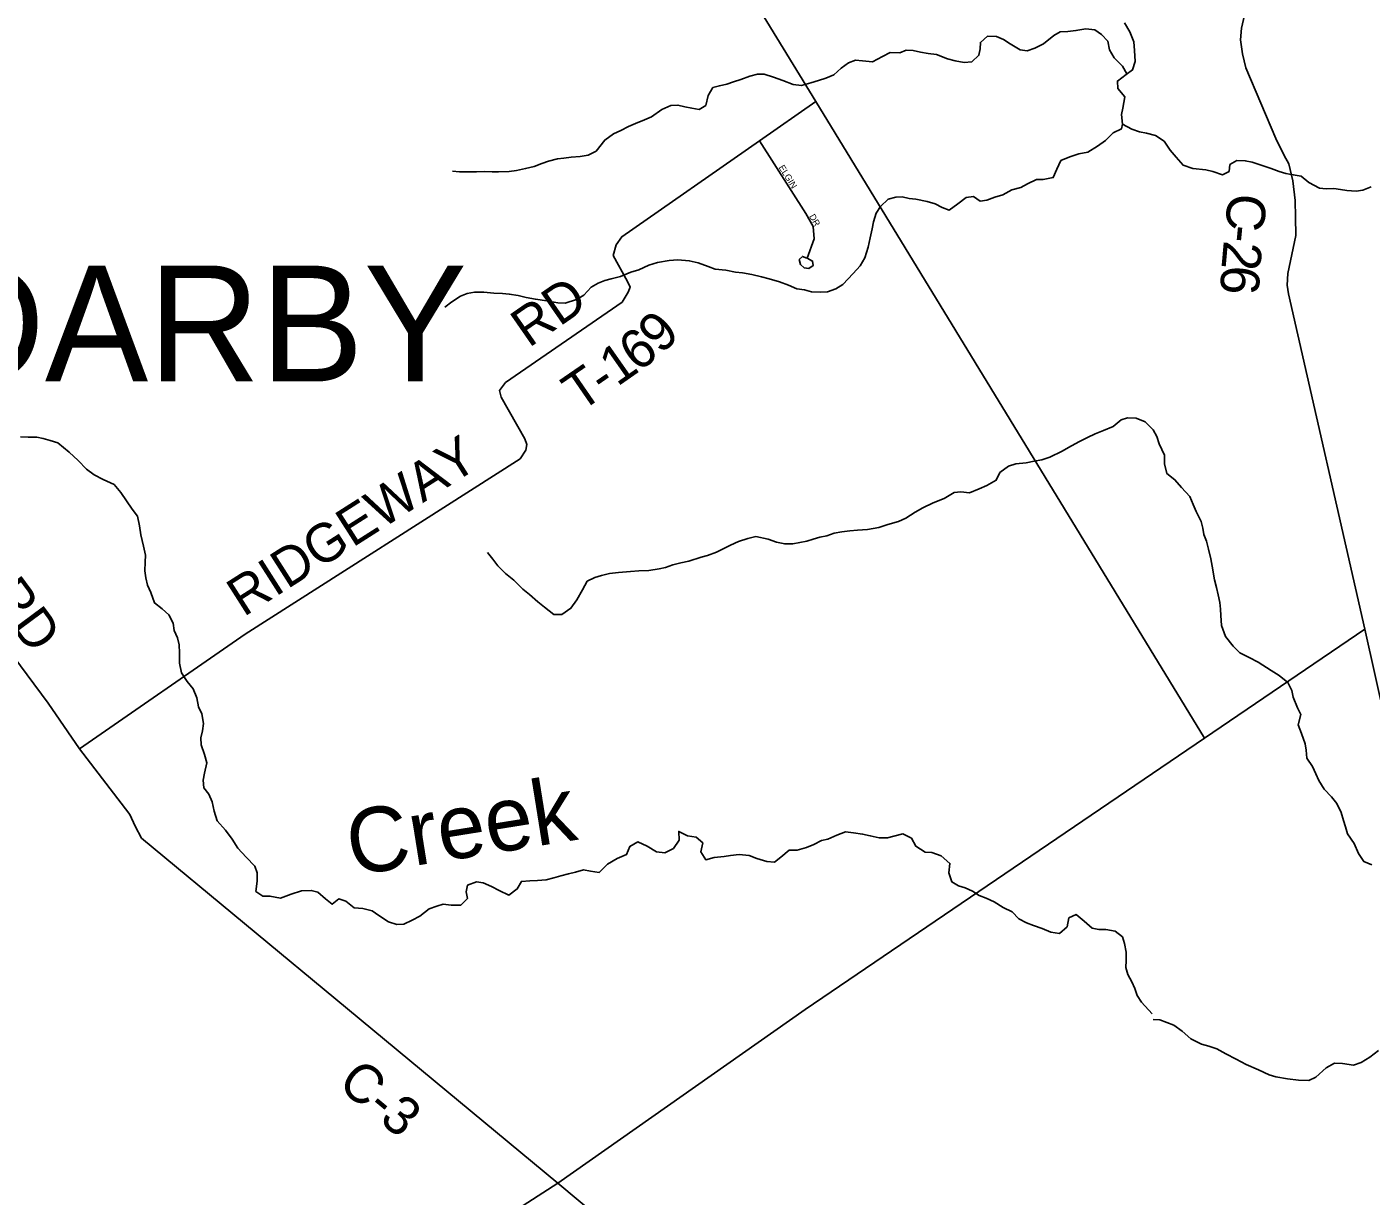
# Model space of a CAD drawing. Extents: x 1643459 to 2064572, y 425441 to 780708.
# Drawn here: x 1773348 to 1783780, y 636662 to 645736 of the extents above; entities that cross this region are included whole.
import ezdxf

# ---------------------------------------------------------------- set-up
doc = ezdxf.new("R2010")
doc.units = 0
for name, color, linetype in [('GM_X_Adjacent_County_Text', 7, 'Continuous'), ('GM_X_County', 7, 'Continuous'), ('GM_X_Interchange_Ramps', 7, 'Continuous'), ('GM_X_Major_River', 7, 'Continuous'), ('GM_X_Major_River_Text', 7, 'Continuous'), ('GM_X_Minor_Lake', 7, 'Continuous'), ('GM_X_Section_Text', 7, 'Continuous'), ('GM_X_Township', 7, 'Continuous'), ('GM_X_US_Route', 7, 'Continuous')]:
    doc.layers.add(name, color=color, linetype=linetype)

msp = doc.modelspace()

# ---------------------------------------------------------------- linework, layer by layer
at = {"layer": 'GM_X_County'}
msp.add_lwpolyline([(1779401, 643942), (1779367, 643955), (1779342, 643932), (1779351, 643892), (1779380, 643867), (1779416, 643862), (1779449, 643883), (1779445, 643919), (1779403, 643942), (1779459, 644090), (1779450, 644186), (1779392, 644289), (1779033, 644851)], dxfattribs=at)
at = {"layer": 'GM_X_Major_River_Text'}
for points in [[(1773772, 654062), (1774788, 652619), (1775038, 652262), (1776783, 649553), (1777290, 648723), (1777849, 647808), (1778173, 647353), (1778816, 646270), (1779041, 645859), (1779471, 645156), (1782488, 640217)], [(1779471, 645156), (1779033, 644851), (1777965, 644107), (1777921, 644045), (1777899, 643961), (1778009, 643759), (1778029, 643717), (1778015, 643677), (1777967, 643599), (1777063, 642975), (1777017, 642915), (1777029, 642863), (1777213, 642538), (1777229, 642494), (1777221, 642450), (1777177, 642384), (1775043, 641022), (1773757, 640134)]]:
    msp.add_lwpolyline(points, dxfattribs=at)
at = {"layer": 'GM_X_Minor_Lake'}
for points in [[(1782846, 646043), (1782774, 645727), (1782766, 645635), (1782783, 645526), (1782809, 645418), (1783041, 644870), (1783105, 644738), (1783143, 644674), (1783173, 644541), (1783191, 644389), (1783194, 644259), (1783196, 644117), (1783134, 643823), (1783128, 643731), (1783140, 643665), (1783732, 641062), (1783977, 639959), (1784007, 639839), (1784401, 639056), (1784510, 638910), (1784732, 638676), (1785248, 638277), (1786244, 637616)], [(1772273, 642156), (1773514, 640487), (1773757, 640134), (1774079, 639712), (1774147, 639624), (1774189, 639534), (1774237, 639440), (1775835, 638115), (1777468, 636763)], [(1777468, 636763), (1779387, 638110), (1782488, 640217), (1783732, 641062)], [(1770002, 630601), (1770093, 632687), (1770093, 632721), (1770134, 632749), (1771962, 632990), (1772032, 633004), (1772074, 633002), (1772101, 633006), (1772127, 633040), (1772487, 633676), (1772513, 633722), (1772573, 633755), (1773397, 634171), (1773574, 634266), (1774462, 634825), (1777468, 636763)], [(1777468, 636763), (1779643, 634945), (1780949, 633862), (1781378, 633511), (1781747, 633198), (1782023, 632988), (1782140, 632869), (1782345, 632675), (1782447, 632557), (1782718, 632238), (1783038, 631872), (1783242, 631666), (1783288, 631620)]]:
    msp.add_lwpolyline(points, dxfattribs=at)
at = {"layer": 'GM_X_US_Route'}
for points in [[(1781884, 645372), (1781852, 645430), (1781786, 645495), (1781751, 645559), (1781737, 645625), (1781689, 645677), (1781635, 645714), (1781567, 645722), (1781489, 645708), (1781427, 645699), (1781367, 645697), (1781317, 645669), (1781238, 645605), (1781170, 645572), (1781110, 645550), (1781056, 645558), (1780980, 645605), (1780926, 645639), (1780872, 645661), (1780802, 645664), (1780748, 645616), (1780746, 645566), (1780737, 645516), (1780681, 645464), (1780623, 645460), (1780551, 645473), (1780493, 645489), (1780407, 645523), (1780343, 645530), (1780283, 645540), (1780225, 645554), (1780173, 645556), (1780123, 645535), (1780047, 645537), (1779989, 645505), (1779910, 645466), (1779834, 645472), (1779778, 645478), (1779724, 645457), (1779668, 645415), (1779610, 645363), (1779548, 645337), (1779491, 645321), (1779431, 645302), (1779359, 645280), (1779295, 645290), (1779215, 645319), (1779141, 645347), (1779069, 645368), (1779017, 645368), (1778959, 645354), (1778889, 645328), (1778831, 645309), (1778779, 645291), (1778723, 645279), (1778672, 645265), (1778634, 645204), (1778618, 645126), (1778566, 645096), (1778508, 645106), (1778454, 645116), (1778400, 645129), (1778345, 645127), (1778275, 645095), (1778195, 645037), (1778141, 645016), (1778071, 644986), (1778016, 644964), (1777958, 644933), (1777900, 644907), (1777832, 644857), (1777765, 644771), (1777705, 644740), (1777641, 644730), (1777573, 644726), (1777515, 644718), (1777465, 644711), (1777395, 644693), (1777345, 644675), (1777284, 644652), (1777218, 644636), (1777148, 644622), (1777092, 644614), (1777008, 644611), (1776958, 644611), (1776896, 644613), (1776838, 644612), (1776760, 644610), (1776706, 644610), (1776650, 644617)], [(1783782, 644496), (1783716, 644470), (1783664, 644461), (1783592, 644465), (1783542, 644475), (1783492, 644481), (1783431, 644478), (1783379, 644484), (1783298, 644528), (1783238, 644577), (1783176, 644589), (1783118, 644599), (1783066, 644614), (1783004, 644636), (1782928, 644662), (1782858, 644685), (1782804, 644697), (1782738, 644699), (1782684, 644667), (1782679, 644615), (1782627, 644588), (1782551, 644614), (1782497, 644626), (1782397, 644637), (1782321, 644663), (1782267, 644725), (1782220, 644780), (1782174, 644850), (1782108, 644892), (1782036, 644911), (1781984, 644921), (1781922, 644943), (1781852, 644980), (1781842, 645056), (1781853, 645106), (1781869, 645192), (1781815, 645258), (1781812, 645316), (1781878, 645366), (1781928, 645402), (1781948, 645468), (1781945, 645552), (1781939, 645620), (1781907, 645698), (1781866, 645767)], [(1781852, 644980), (1781842, 644944), (1781778, 644914), (1781718, 644854), (1781657, 644810), (1781583, 644765), (1781511, 644751), (1781441, 644727), (1781373, 644698), (1781340, 644632), (1781314, 644566), (1781234, 644552), (1781184, 644552), (1781113, 644519), (1781063, 644489), (1780991, 644471), (1780921, 644432), (1780859, 644414), (1780797, 644390), (1780747, 644384), (1780695, 644419), (1780637, 644413), (1780574, 644363), (1780506, 644313), (1780450, 644334), (1780396, 644364), (1780334, 644380), (1780246, 644399), (1780196, 644403), (1780142, 644417), (1780092, 644414), (1780032, 644400), (1779972, 644342), (1779939, 644290), (1779919, 644222), (1779907, 644168), (1779893, 644098), (1779878, 644026), (1779852, 643944), (1779814, 643882), (1779761, 643821), (1779681, 643737), (1779625, 643703), (1779562, 643679), (1779506, 643678), (1779438, 643680), (1779384, 643696), (1779324, 643703), (1779258, 643731), (1779190, 643757), (1779108, 643782), (1779048, 643796), (1778974, 643814), (1778902, 643827), (1778848, 643833), (1778772, 643847), (1778690, 643856), (1778634, 643876), (1778558, 643906), (1778488, 643921), (1778400, 643927), (1778332, 643922), (1778242, 643908), (1778176, 643886), (1778098, 643851), (1778036, 643833), (1777955, 643799), (1777883, 643782), (1777833, 643768), (1777781, 643746), (1777727, 643716), (1777669, 643655), (1777614, 643621), (1777526, 643591), (1777468, 643595), (1777382, 643610), (1777294, 643622), (1777224, 643635), (1777160, 643651), (1777092, 643663), (1777040, 643666), (1776972, 643670), (1776894, 643678), (1776822, 643677), (1776766, 643667), (1776712, 643645), (1776645, 643601), (1776591, 643560)], [(1783785, 639234), (1783723, 639259), (1783682, 639321), (1783648, 639399), (1783598, 639473), (1783582, 639528), (1783567, 639578), (1783547, 639640), (1783515, 639708), (1783473, 639760), (1783415, 639819), (1783374, 639887), (1783352, 639939), (1783326, 639997), (1783282, 640062), (1783275, 640122), (1783269, 640172), (1783239, 640252), (1783215, 640320), (1783234, 640400), (1783208, 640452), (1783176, 640533), (1783164, 640585), (1783135, 640649), (1783067, 640703), (1783005, 640740), (1782905, 640806), (1782835, 640841), (1782761, 640879), (1782710, 640931), (1782650, 641006), (1782618, 641090), (1782614, 641168), (1782611, 641218), (1782605, 641268), (1782593, 641328), (1782581, 641386), (1782566, 641444), (1782546, 641551), (1782536, 641607), (1782517, 641683), (1782503, 641745), (1782483, 641797), (1782475, 641847), (1782461, 641897), (1782422, 641976), (1782398, 642030), (1782374, 642092), (1782310, 642162), (1782257, 642221), (1782195, 642269), (1782177, 642345), (1782177, 642413), (1782136, 642500), (1782116, 642556), (1782088, 642608), (1782026, 642670), (1781956, 642699), (1781890, 642703), (1781840, 642687), (1781778, 642634), (1781704, 642604), (1781638, 642578), (1781579, 642550), (1781511, 642517), (1781433, 642471), (1781383, 642443), (1781287, 642398), (1781226, 642376), (1781166, 642366), (1781102, 642354), (1781024, 642345), (1780966, 642327), (1780898, 642277), (1780871, 642217), (1780799, 642176), (1780739, 642150), (1780663, 642120), (1780597, 642129), (1780545, 642123), (1780468, 642075), (1780382, 642042), (1780300, 642004), (1780242, 641970), (1780169, 641924), (1780113, 641897), (1780029, 641873), (1779959, 641851), (1779873, 641836), (1779793, 641830), (1779735, 641824), (1779673, 641817), (1779612, 641807), (1779556, 641787), (1779502, 641776)], [(1776768, 638972), (1776715, 638920), (1776641, 638920), (1776579, 638927), (1776529, 638913), (1776471, 638891), (1776397, 638834), (1776338, 638804), (1776274, 638772), (1776220, 638770), (1776154, 638791), (1776080, 638841), (1776028, 638877), (1775954, 638894), (1775888, 638898), (1775824, 638952), (1775770, 638969), (1775718, 638927), (1775666, 638969), (1775607, 639022), (1775555, 639034), (1775480, 639030), (1775398, 639005), (1775316, 638975), (1775234, 638991), (1775180, 638990), (1775124, 639026), (1775136, 639106), (1775135, 639172), (1775117, 639222), (1775049, 639293), (1774985, 639363), (1774940, 639433), (1774888, 639502), (1774824, 639574), (1774802, 639650), (1774785, 639722), (1774759, 639781), (1774721, 639831), (1774717, 639891), (1774726, 639945), (1774744, 640025), (1774726, 640089), (1774701, 640165), (1774697, 640219), (1774711, 640273), (1774719, 640329), (1774706, 640404), (1774680, 640458), (1774668, 640528), (1774638, 640598), (1774591, 640656), (1774547, 640723), (1774533, 640799), (1774533, 640879), (1774530, 640941), (1774516, 640995), (1774492, 641051), (1774482, 641109), (1774449, 641174), (1774397, 641220), (1774339, 641266), (1774311, 641347), (1774283, 641403), (1774272, 641459), (1774262, 641515), (1774266, 641581), (1774268, 641635), (1774253, 641705), (1774233, 641795), (1774221, 641864), (1774206, 641938), (1774166, 641992), (1774122, 642058), (1774076, 642123), (1774025, 642185), (1773941, 642223), (1773869, 642260), (1773811, 642304), (1773747, 642372), (1773677, 642435), (1773588, 642509), (1773528, 642526), (1773474, 642542), (1773424, 642552), (1773357, 642553), (1773297, 642555)], [(1779502, 641776), (1779450, 641760), (1779400, 641744), (1779292, 641724), (1779230, 641723), (1779166, 641737), (1779100, 641761), (1779006, 641780), (1778942, 641766), (1778871, 641741), (1778809, 641713), (1778751, 641685), (1778701, 641659), (1778631, 641634), (1778581, 641620), (1778484, 641590), (1778424, 641577), (1778362, 641561), (1778304, 641541), (1778254, 641529), (1778174, 641518), (1778098, 641514), (1778032, 641510), (1777940, 641501), (1777869, 641493), (1777807, 641479), (1777755, 641462), (1777697, 641434), (1777659, 641368), (1777616, 641290), (1777570, 641224), (1777500, 641177), (1777438, 641175), (1777364, 641233), (1777312, 641274), (1777248, 641330), (1777196, 641372), (1777128, 641441), (1777063, 641493), (1777003, 641553), (1776965, 641604), (1776923, 641658)], [(1782080, 638077), (1781997, 638168), (1781965, 638220), (1781947, 638272), (1781924, 638326), (1781892, 638382), (1781876, 638437), (1781878, 638491), (1781879, 638555), (1781867, 638623), (1781851, 638673), (1781793, 638717), (1781721, 638730), (1781667, 638732), (1781615, 638742), (1781553, 638796), (1781491, 638847), (1781435, 638821), (1781421, 638753), (1781361, 638701), (1781295, 638710), (1781227, 638740), (1781161, 638762), (1781107, 638783), (1781047, 638813), (1780995, 638867), (1780925, 638902), (1780855, 638946), (1780793, 638974), (1780739, 638995), (1780686, 639029), (1780630, 639055), (1780578, 639071), (1780526, 639100), (1780502, 639172), (1780512, 639244), (1780444, 639304), (1780371, 639329), (1780320, 639331), (1780247, 639377), (1780213, 639440), (1780147, 639474), (1780077, 639456), (1780027, 639442), (1779963, 639443), (1779893, 639459), (1779833, 639471), (1779763, 639480), (1779701, 639488), (1779634, 639462), (1779564, 639431), (1779514, 639421), (1779454, 639391), (1779398, 639367), (1779326, 639348), (1779264, 639348), (1779199, 639292), (1779149, 639254), (1779091, 639259), (1779013, 639283), (1778953, 639306), (1778875, 639314), (1778809, 639306), (1778759, 639298), (1778683, 639289), (1778617, 639273), (1778577, 639335), (1778595, 639403), (1778541, 639448), (1778475, 639458), (1778407, 639492), (1778411, 639424), (1778365, 639360), (1778299, 639325), (1778235, 639333), (1778163, 639377), (1778089, 639412), (1778028, 639376), (1778002, 639314), (1777928, 639282), (1777854, 639239), (1777789, 639173), (1777723, 639183), (1777667, 639194), (1777605, 639176), (1777551, 639164), (1777491, 639148), (1777437, 639131), (1777379, 639117), (1777311, 639111), (1777251, 639110), (1777186, 639104), (1777154, 639046), (1777088, 638998), (1777014, 639035), (1776954, 639065), (1776890, 639093), (1776836, 639102), (1776768, 639076), (1776756, 639024), (1776768, 638972)], [(1783837, 637791), (1783770, 637739), (1783702, 637699), (1783644, 637679), (1783559, 637690), (1783497, 637694), (1783431, 637658), (1783352, 637586), (1783296, 637559), (1783216, 637561), (1783132, 637572), (1783041, 637588), (1782989, 637604), (1782906, 637641), (1782810, 637684), (1782734, 637726), (1782652, 637767), (1782584, 637805), (1782522, 637826), (1782464, 637840), (1782382, 637883), (1782314, 637943), (1782248, 637988), (1782140, 638029), (1782090, 638033)]]:
    msp.add_lwpolyline(points, dxfattribs=at)

# ---------------------------------------------------------------- texts
at = {"layer": 'GM_X_Adjacent_County_Text'}
msp.add_text('DARBY', height=900, rotation=0, dxfattribs=at).set_placement((1772618, 642984))
at = {"layer": 'GM_X_Interchange_Ramps'}
msp.add_text('Creek', height=500, rotation=9.105, dxfattribs=at).set_placement((1775872, 639147))
at = {"layer": 'GM_X_Major_River'}
for s, rotation, p in [('RD', 34.788, (1777243, 643241)), ('9', 43.9594, (1778269, 643188)), ('6', 36.461, (1778087, 643051)), ('1', 34.986, (1777929, 642940)), ('T', 34.5328, (1777641, 642741)), ('-', 34.6382, (1777826, 642869)), ('RIDGEWAY', 32.5006, (1775029, 641153))]:
    msp.add_text(s, height=300, rotation=rotation, dxfattribs=at).set_placement(p)
at = {"layer": 'GM_X_Section_Text'}
for s, rotation, p in [('C', 264.4296, (1782674, 644453)), ('-', 264.5134, (1782650, 644208)), ('2', 264.8876, (1782638, 644083)), ('6', 266.4572, (1782621, 643890)), ('RD', 306.5728, (1773045, 641322)), ('C-3', 320.194, (1775749, 637516))]:
    msp.add_text(s, height=300, rotation=rotation, dxfattribs=at).set_placement(p)
at = {"layer": 'GM_X_Township'}
for s, rotation, p in [('ELGIN', 302.1561, (1779180, 644645)), ('DR', 299.3565, (1779417, 644266))]:
    msp.add_text(s, height=50, rotation=rotation, dxfattribs=at).set_placement(p)

doc.saveas('drawing.dxf')
